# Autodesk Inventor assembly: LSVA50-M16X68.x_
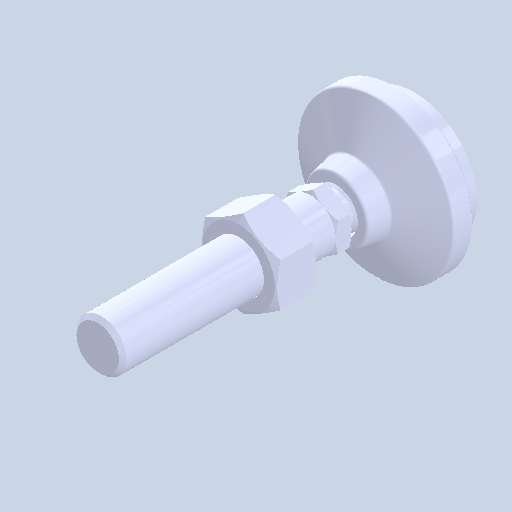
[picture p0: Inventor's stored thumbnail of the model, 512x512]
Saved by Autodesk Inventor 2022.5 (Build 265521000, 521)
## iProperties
Created: 2024-08
Part Number: LSVA50-M16X68.x_
Document SubType Name: Assembly
Designer: ImaoCorp
Author: ImaoCorp
Sending System: SOLIDWORKS 2022-2022290
MC: AMD64
MC_MODEL: Intel64 Family 6 Model 60 Stepping 3, GenuineIntel
OS: Windows_NT
FRU: Parasolid Version 33.1, build 260,  4-25-2022
FORMAT: text
GUISE: transmit
KEY: FILELSVA50-M16X68.x_t
DATE: Fri Aug 23 16:08:44 2024
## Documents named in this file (4)
- X:\14_SW2022-Inv2022\06_2024-10新製品(SME)\ELS_データ\l\lsva50-m16x68\LSVA50-M16X68.x_.iam
- X:\14_SW2022-Inv2022\06_2024-10新製品(SME)\ELS_データ\l\lsva50-m16x68\LSVA50-M16X68_01.ipt
- X:\14_SW2022-Inv2022\06_2024-10新製品(SME)\ELS_データ\l\lsva50-m16x68\LSVA50-M16X68_02.ipt
- X:\14_SW2022-Inv2022\06_2024-10新製品(SME)\ELS_データ\l\lsva50-m16x68\LSVA50-M16X68_03.ipt
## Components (3 placed, 3 different names)
1. LSVA50-M16X68_01
2. LSVA50-M16X68_02
3. LSVA50-M16X68_03
